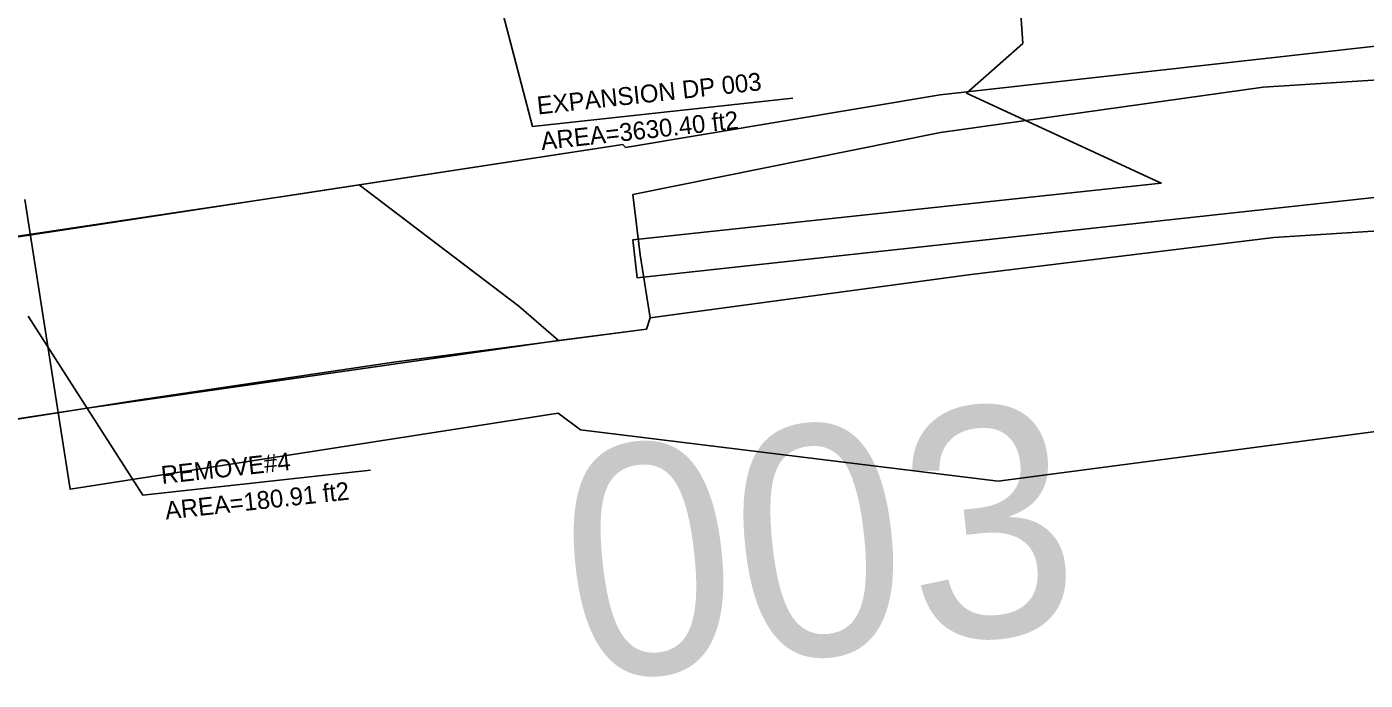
# Model space of a CAD drawing. Extents: x 1509538 to 1510847, y 401283 to 402022.
# Drawn here: x 1509974.7 to 1510184.5, y 401571.3 to 401673.7 of the extents above; entities that cross this region are included whole.
import ezdxf

# ---------------------------------------------------------------- set-up
doc = ezdxf.new("R2010")
doc.units = 0
for name, color, linetype in [('LAWE_P_T', 7, 'Continuous'), ('LDEFAULT_P', 7, 'Continuous'), ('Level 21', 7, 'Continuous'), ('Level 24', 7, 'Continuous'), ('Level 25', 7, 'Continuous'), ('Level 3', 7, 'Continuous'), ('Level 4', 7, 'Continuous')]:
    doc.layers.add(name, color=color, linetype=linetype)

msp = doc.modelspace()

# ---------------------------------------------------------------- linework, layer by layer
at = {"layer": 'LAWE_P_T'}
msp.add_lwpolyline([(1509974.91, 401628.35), (1509992.87, 401600.28), (1510028.57, 401604.17)], dxfattribs=at)
at = {"layer": 'LDEFAULT_P'}
msp.add_lwpolyline([(1510048.22, 401680.04), (1510053.95, 401658.05), (1510094.78, 401662.5)], dxfattribs=at)
at = {"layer": 'Level 21'}
msp.add_lwpolyline([(1510242.15, 401688.33), (1510240.12, 401676.82), (1510238.33, 401670.41), (1510235.71, 401665.22), (1510232.46, 401660.96), (1510228.6, 401657.18), (1510223.92, 401653.49), (1510219.07, 401651.42), (1510213.42, 401650.8), (1510199.34, 401648.36), (1510124.09, 401640.16), (1510070.35, 401634.35), (1510069.7, 401640.31), (1510152.54, 401649.19), (1510122.02, 401663.28), (1510130.83, 401671.08), (1510129.8, 401686.5), (1510116.98, 401685.56), (1510115.9, 401688.49), (1510149.69, 401690.52), (1510186.34, 401691), (1510223.03, 401690)], close=True, dxfattribs=at)
at = {"layer": 'Level 24'}
msp.add_lwpolyline([(1510422.96, 401609.85), (1510373.65, 401595.47), (1510320.84, 401595.24), (1510273.34, 401614.89), (1510252.89, 401621.29), (1510233.84, 401623.61), (1510221.68, 401620.37), (1510216.62, 401624.36), (1510199.65, 401612.04), (1510126.95, 401602.48), (1510061.48, 401610.5), (1510058.01, 401613.13), (1509981.47, 401601.19), (1509974.39, 401646.63)], dxfattribs=at)
at = {"layer": 'Level 25'}
msp.add_lwpolyline([(1510026.79, 401648.9), (1510037.69, 401640.62), (1510051.8, 401629.9), (1510058.05, 401624.5), (1509984.14, 401613.93), (1509867.79, 401596.15), (1509863.73, 401624.03)], close=True, dxfattribs=at)
at = {"layer": 'Level 3'}
for p in [(1510058.05, 401624.5), (1510051.8, 401629.9)]:
    msp.add_line(p, (1510051.8, 401629.9), dxfattribs=at)
at = {"layer": 'Level 4'}
for p, q in [((1510117.88, 401663), (1510068.52, 401654.76)), ((1510068.15, 401655.21), (1510026.79, 401648.9)), ((1510068.52, 401654.76), (1510068.15, 401655.21)), ((1510068.52, 401654.76), (1510068.15, 401655.21)), ((1510068.52, 401654.76), (1510068.15, 401655.21)), ((1510026.79, 401648.9), (1510026.79, 401648.9)), ((1510026.79, 401648.9), (1510026.79, 401648.9)), ((1510026.79, 401648.9), (1510026.79, 401648.9)), ((1510026.79, 401648.9), (1510051.8, 401629.9)), ((1510069.7, 401647.38), (1510069.7, 401647.38)), ((1510070.82, 401637.95), (1510069.7, 401647.38)), ((1510072.41, 401628.04), (1510070.82, 401637.95)), ((1510072.41, 401628.04), (1510070.82, 401637.95)), ((1510051.8, 401629.9), (1510058.05, 401624.5)), ((1510071.84, 401626.31), (1510072.41, 401628.04)), ((1510071.84, 401626.31), (1510072.41, 401628.04)), ((1510058.05, 401624.5), (1510071.84, 401626.31))]:
    msp.add_line(p, q, dxfattribs=at)
for points in [[(1510271.44, 401667.79), (1510193.59, 401671.47), (1510117.88, 401663), (1510068.52, 401654.76)], [(1510271.44, 401667.79), (1510193.59, 401671.47), (1510117.88, 401663), (1510068.52, 401654.76)], [(1510271.44, 401667.79), (1510193.59, 401671.47), (1510117.88, 401663)], [(1510420.35, 401661.34), (1510371.76, 401662.64), (1510321.9, 401665.44), (1510271.44, 401667.79), (1510220.39, 401667.36), (1510212.05, 401667), (1510168.51, 401664.21), (1510117.95, 401657.12), (1510069.7, 401647.38)], [(1510069.7, 401647.38), (1510117.95, 401657.12), (1510168.51, 401664.21), (1510212.05, 401667), (1510220.39, 401667.36), (1510271.44, 401667.79)], [(1510168.51, 401664.21), (1510212.05, 401667), (1510220.39, 401667.36)], [(1510069.7, 401647.38), (1510117.95, 401657.12), (1510168.51, 401664.21)], [(1510068.15, 401655.21), (1510017.64, 401647.51), (1509967.63, 401640.04), (1509894.45, 401628.81), (1509861.08, 401623.62)], [(1510068.15, 401655.21), (1510068.15, 401655.21)], [(1510069.7, 401647.38), (1510070.82, 401637.95), (1510072.41, 401628.04), (1510122.3, 401634.81), (1510170.19, 401640.65), (1510220.23, 401643.86), (1510269.72, 401644.29), (1510320.63, 401641.42), (1510370.24, 401637.87), (1510421.73, 401637.03), (1510472.3, 401638.25), (1510523.24, 401640.81), (1510571.7, 401643.53), (1510601.13, 401645.2)], [(1510070.82, 401637.95), (1510069.7, 401647.38)], [(1509865.36, 401595.79), (1509909.05, 401602.33), (1509950.02, 401608.51), (1509992.39, 401615.24), (1510032.23, 401621.12), (1510071.84, 401626.31)]]:
    msp.add_lwpolyline(points, dxfattribs=at)

# ---------------------------------------------------------------- texts
at = {"layer": 'LAWE_P_T'}
for s, p in [('REMOVE#4', (1509995.89, 401602.02)), ('AREA=180.91 ft2', (1509996.5, 401596.45))]:
    msp.add_text(s, height=2.8, rotation=6.2219, dxfattribs=at).set_placement(p)
at = {"layer": 'LDEFAULT_P'}
for s, p in [('EXPANSION DP 003', (1510054.82, 401659.92)), ('AREA=3630.40 ft2', (1510055.43, 401654.35))]:
    msp.add_text(s, height=2.8, rotation=6.2219, dxfattribs=at).set_placement(p)
at = {"layer": 'Level 3'}
msp.add_text('003', height=36, rotation=6.2215, dxfattribs=at).set_placement((1510060.81, 401570.96))

doc.saveas('drawing.dxf')
